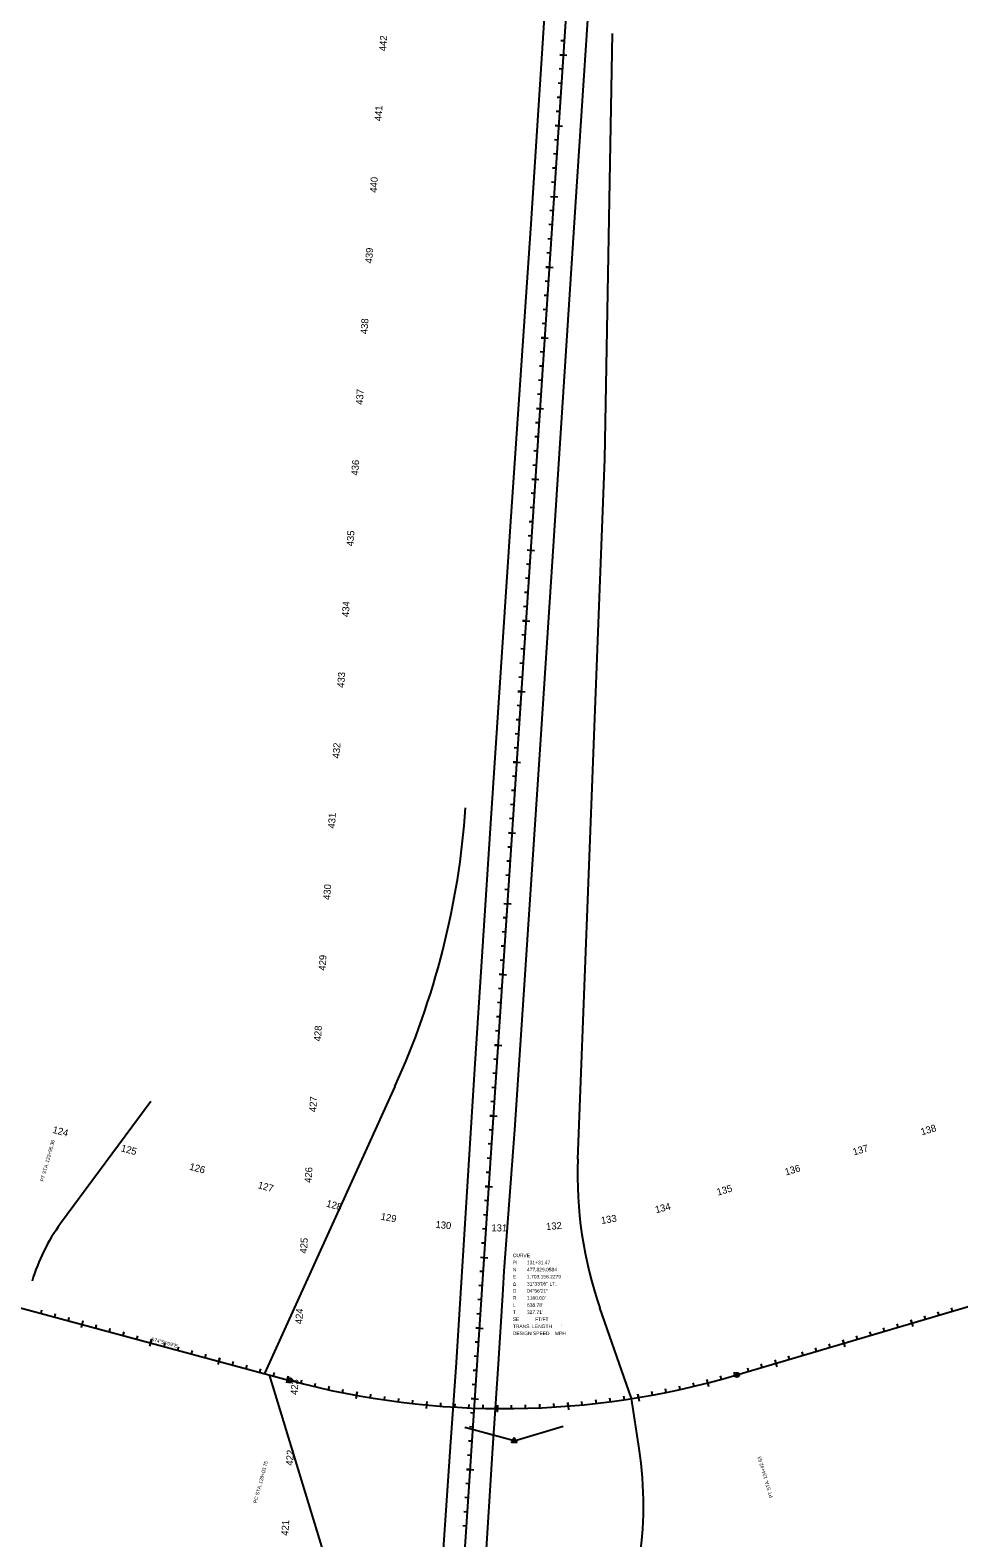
# Model space of a CAD drawing. Extents: x 1699999 to 1705087, y 475568 to 482652.
# Drawn here: x 1702475 to 1703786, y 477692 to 479819 of the extents above; entities that cross this region are included whole.
import ezdxf

# ---------------------------------------------------------------- set-up
doc = ezdxf.new("R2010")
doc.units = 0
for name, color, linetype in [('Default', 7, 'Continuous'), ('DES - DTM - Boundary', 7, 'Continuous'), ('DES - DTM - Ground', 7, 'Continuous'), ('DES - DTM - Points - High', 7, 'Continuous'), ('DESIGN - TYPICAL - Guardrail', 7, 'Continuous'), ('TC_Aggregate', 7, 'Continuous')]:
    doc.layers.add(name, color=color, linetype=linetype)

msp = doc.modelspace()

# ---------------------------------------------------------------- linework, layer by layer
at = {"layer": 'Default'}
for p, q in [((1703065.1, 477316.2), (1703415.3, 482625.1)), ((1703248.2, 478226.2), (1703286, 479214.2)), ((1702990, 478329), (1702806, 477924)), ((1703129.1, 478287.3), (1703129.1, 478286.5)), ((1702447.5, 478020.6), (1702841.8, 477914.3)), ((1703323.8, 477888.5), (1703279.3, 478016.7)), ((1703334.6, 477818.2), (1703323.8, 477888.5))]:
    msp.add_line(p, q, dxfattribs=at)
for centre, radius, start, end in [((1703820.7, 478204.3), 573, 177.8081, 199.1047), ((1702727.8, 477980.8), 260.4, 143.5571, 163.5778), ((1703143.6, 479034.4), 1160, 254.9193, 286.4705), ((1702819.9, 477738.6), 520.9, 332.348, 8.7908)]:
    msp.add_arc(centre, radius, start, end, dxfattribs=at)
at = {"layer": 'DES - DTM - Ground'}
for p, q in [((1703065.1, 477316.2), (1703415.3, 482625.1)), ((1703286, 479214.2), (1703297, 479814.6)), ((1703248.2, 478226.2), (1703286, 479214.2)), ((1702990, 478329), (1702806, 477924)), ((1703472.5, 477922), (1704846.9, 478328.4)), ((1702645.4, 478307.7), (1702518.3, 478135.5)), ((1702447.5, 478020.6), (1702841.8, 477914.3)), ((1703323.8, 477888.5), (1703279.3, 478016.7)), ((1702812.7, 477922.2), (1702891.6, 477662.9)), ((1703334.6, 477818.2), (1703323.8, 477888.5))]:
    msp.add_line(p, q, dxfattribs=at)
for points in [[(1703117.2, 477646.5), (1703128.4, 477818.7), (1703136.1, 477937.6), (1703142.4, 478034.3), (1703144.2, 478068.5), (1703147.9, 478118.3), (1703159.1, 478267.9), (1703195.1, 478804.3), (1703212.4, 479069.6), (1703246.7, 479598.7), (1703259.7, 479798.3), (1703310.9, 480575.7)], [(1702792.5, 475614.8), (1702811.9, 475706.1), (1702823.5, 475760.9), (1702852.3, 475908.3), (1702864.3, 475969.8), (1702898.6, 476166.8), (1702930.7, 476366.1), (1702944.7, 476465.1), (1702959.1, 476566.7), (1702978.3, 476715.2), (1702996.2, 476873.4), (1703005.9, 476974.9), (1703015.7, 477085.1), (1703027.3, 477226.9), (1703041.4, 477426.6), (1703058.8, 477682.8), (1703068.5, 477820.5), (1703076.7, 477939.3), (1703102.2, 478346.2), (1703125.6, 478707.3), (1703153.6, 479126.1), (1703182.2, 479545.9), (1703224.8, 480202.3)]]:
    msp.add_lwpolyline(points, dxfattribs=at)
for centre, radius, start, end in [((1701946.8, 478803.1), 1145.9, 335.5607, 355.9395), ((1703820.7, 478204.3), 573, 177.8081, 199.1047), ((1702727.8, 477980.8), 260.4, 143.5571, 163.5778), ((1703143.6, 479034.4), 1160, 254.9193, 286.4705), ((1702819.9, 477738.6), 520.9, 332.348, 8.7908)]:
    msp.add_arc(centre, radius, start, end, dxfattribs=at)
at = {"layer": 'DES - DTM - Points - High'}
for p, q in [((1703229.2, 479804), (1703224.2, 479804.4)), ((1703222.9, 479784.4), (1703232.8, 479783.8)), ((1703226.5, 479764.1), (1703221.6, 479764.5)), ((1703223.9, 479724.2), (1703218.9, 479724.5)), ((1703225.2, 479744.2), (1703220.2, 479744.5)), ((1703222.6, 479704.3), (1703217.6, 479704.6)), ((1703216.3, 479684.6), (1703226.3, 479684)), ((1703219.9, 479664.3), (1703215, 479664.7)), ((1703218.6, 479644.4), (1703213.7, 479644.7)), ((1703217.3, 479624.4), (1703212.3, 479624.8)), ((1703216, 479604.5), (1703211, 479604.8)), ((1703209.7, 479584.8), (1703219.7, 479584.2)), ((1703213.4, 479564.6), (1703208.4, 479564.9)), ((1703212, 479544.6), (1703207.1, 479544.9)), ((1703210.7, 479524.6), (1703205.8, 479525)), ((1703209.4, 479504.7), (1703204.4, 479505)), ((1703203.1, 479485.1), (1703213.1, 479484.4)), ((1703206.8, 479464.8), (1703201.8, 479465.1)), ((1703205.5, 479444.8), (1703200.5, 479445.1)), ((1703202.8, 479404.9), (1703197.9, 479405.2)), ((1703204.1, 479424.9), (1703199.2, 479425.2)), ((1703196.5, 479385.3), (1703206.5, 479384.6)), ((1703200.2, 479365), (1703195.2, 479365.3)), ((1703198.9, 479345), (1703193.9, 479345.4)), ((1703197.6, 479325.1), (1703192.6, 479325.4)), ((1703196.3, 479305.1), (1703191.3, 479305.5)), ((1703189.9, 479285.5), (1703199.9, 479284.8)), ((1703193.6, 479265.2), (1703188.6, 479265.5)), ((1703192.3, 479245.3), (1703187.3, 479245.6)), ((1703191, 479225.3), (1703186, 479225.6)), ((1703189.7, 479205.3), (1703184.7, 479205.7)), ((1703183.4, 479185.7), (1703193.3, 479185.1)), ((1703187, 479165.4), (1703182.1, 479165.8)), ((1703185.7, 479145.5), (1703180.8, 479145.8)), ((1703184.4, 479125.5), (1703179.4, 479125.8)), ((1703183.1, 479105.6), (1703178.1, 479105.9)), ((1703180.5, 479065.6), (1703175.5, 479066)), ((1703176.8, 479085.9), (1703186.8, 479085.3)), ((1703179.1, 479045.7), (1703174.2, 479046)), ((1703177.8, 479025.7), (1703172.9, 479026.1)), ((1703176.5, 479005.8), (1703171.5, 479006.1)), ((1703170.2, 478986.1), (1703180.2, 478985.5)), ((1703173.9, 478965.9), (1703168.9, 478966.2)), ((1703172.6, 478945.9), (1703167.6, 478946.2)), ((1703171.2, 478925.9), (1703166.3, 478926.3)), ((1703169.9, 478906), (1703165, 478906.3)), ((1703163.6, 478886.4), (1703173.6, 478885.7)), ((1703167.3, 478866.1), (1703162.3, 478866.4)), ((1703166, 478846.1), (1703161, 478846.4)), ((1703164.7, 478826.2), (1703159.7, 478826.5)), ((1703163.3, 478806.2), (1703158.4, 478806.5)), ((1703157, 478786.6), (1703167, 478785.9)), ((1703159.4, 478746.3), (1703154.4, 478746.7)), ((1703160.7, 478766.3), (1703155.7, 478766.6)), ((1703158.1, 478726.4), (1703153.1, 478726.7)), ((1703156.8, 478706.4), (1703151.8, 478706.8)), ((1703150.5, 478686.8), (1703160.4, 478686.1)), ((1703154.1, 478666.5), (1703149.2, 478666.8)), ((1703152.8, 478646.6), (1703147.8, 478646.9)), ((1703151.5, 478626.6), (1703146.5, 478626.9)), ((1703150.2, 478606.6), (1703145.2, 478607)), ((1703143.9, 478587), (1703153.8, 478586.4)), ((1703147.5, 478566.7), (1703142.6, 478567.1)), ((1703146.2, 478546.8), (1703141.3, 478547.1)), ((1703144.9, 478526.8), (1703139.9, 478527.1)), ((1703143.6, 478506.9), (1703138.6, 478507.2)), ((1703137.3, 478487.2), (1703147.3, 478486.6)), ((1703141, 478466.9), (1703136, 478467.3)), ((1703138.3, 478427), (1703133.4, 478427.4)), ((1703139.6, 478447), (1703134.7, 478447.3)), ((1703137, 478407.1), (1703132, 478407.4)), ((1703130.7, 478387.4), (1703140.7, 478386.8)), ((1703134.4, 478367.2), (1703129.4, 478367.5)), ((1703133.1, 478347.2), (1703128.1, 478347.5)), ((1703131.7, 478327.2), (1703126.8, 478327.6)), ((1703130.4, 478307.3), (1703125.5, 478307.6)), ((1703124.1, 478287.7), (1703134.1, 478287)), ((1703127.8, 478267.4), (1703122.8, 478267.7)), ((1703126.5, 478247.4), (1703121.5, 478247.8)), ((1703125.2, 478227.5), (1703120.2, 478227.8)), ((1703123.8, 478207.5), (1703118.9, 478207.8)), ((1703117.5, 478187.9), (1703127.5, 478187.2)), ((1703121.2, 478167.6), (1703116.2, 478167.9)), ((1703119.9, 478147.6), (1703114.9, 478148)), ((1703117.3, 478107.7), (1703112.3, 478108.1)), ((1703118.6, 478127.7), (1703113.6, 478128)), ((1703111, 478088.1), (1703120.9, 478087.4)), ((1703114.6, 478067.8), (1703109.7, 478068.1)), ((1703113.3, 478047.9), (1703108.3, 478048.2)), ((1703112, 478027.9), (1703107, 478028.2)), ((1702490.6, 478009), (1702491.9, 478013.8)), ((1702509.9, 478003.8), (1702511.2, 478008.6)), ((1702529.2, 477998.6), (1702530.5, 478003.4)), ((1703110.7, 478007.9), (1703105.7, 478008.3)), ((1703738.6, 478000.7), (1703737.2, 478005.4)), ((1703757.8, 478006.3), (1703756.3, 478011.1)), ((1703776.9, 478012), (1703775.5, 478016.8)), ((1702549.8, 477998.2), (1702547.2, 477988.5)), ((1702567.8, 477988.1), (1702569.1, 477993)), ((1702587.1, 477982.9), (1702588.4, 477987.8)), ((1702606.4, 477977.7), (1702607.7, 477982.6)), ((1703104.4, 477988.3), (1703114.4, 477987.7)), ((1703661.9, 477978), (1703660.4, 477982.7)), ((1703681, 477983.6), (1703679.6, 477988.4)), ((1703700.2, 477989.3), (1703698.8, 477994.1)), ((1703718, 477999.8), (1703720.8, 477990.2)), ((1702625.8, 477972.5), (1702627, 477977.3)), ((1702646.4, 477972.2), (1702643.8, 477962.5)), ((1702664.4, 477962.1), (1702665.7, 477966.9)), ((1702683.7, 477956.9), (1702685, 477961.7)), ((1703108, 477968), (1703103.1, 477968.4)), ((1703585.1, 477955.3), (1703583.7, 477960.1)), ((1703604.3, 477961), (1703602.9, 477965.7)), ((1703622.1, 477971.4), (1703624.9, 477961.8)), ((1703642.7, 477972.3), (1703641.3, 477977.1)), ((1702703, 477951.7), (1702704.3, 477956.5)), ((1702722.3, 477946.5), (1702723.6, 477951.3)), ((1702742.9, 477946.1), (1702740.3, 477936.5)), ((1702760.9, 477936.1), (1702762.2, 477940.9)), ((1703106.7, 477948.1), (1703101.8, 477948.4)), ((1703526.2, 477943.1), (1703529, 477933.5)), ((1703546.8, 477943.9), (1703545.4, 477948.7)), ((1703566, 477949.6), (1703564.5, 477954.4)), ((1702780.2, 477930.9), (1702781.5, 477935.7)), ((1702799.6, 477925.7), (1702800.9, 477930.5)), ((1702818.9, 477920.5), (1702820.2, 477925.3)), ((1702839.5, 477920.1), (1702836.9, 477910.5)), ((1703105.4, 477928.1), (1703100.4, 477928.4)), ((1703450.8, 477915.8), (1703449.5, 477920.6)), ((1703470.1, 477921.3), (1703468.7, 477926)), ((1703489.2, 477926.9), (1703487.8, 477931.7)), ((1703508.4, 477932.6), (1703507, 477937.4)), ((1702857.5, 477910.2), (1702858.7, 477915)), ((1702876.9, 477905.4), (1702878.1, 477910.3)), ((1702896.4, 477901), (1702897.5, 477905.9)), ((1702916, 477896.9), (1702917, 477901.8)), ((1702936.6, 477898.1), (1702934.8, 477888.2)), ((1703104.1, 477908.2), (1703099.1, 477908.5)), ((1703332.9, 477895), (1703334.5, 477885.1)), ((1703353.4, 477893.5), (1703352.5, 477898.4)), ((1703373, 477897.3), (1703372, 477902.2)), ((1703392.6, 477901.4), (1703391.5, 477906.3)), ((1703412.1, 477905.9), (1703410.9, 477910.7)), ((1703430.3, 477915.5), (1703432.7, 477905.8)), ((1702955.4, 477889.7), (1702956.2, 477894.7)), ((1702975.1, 477886.7), (1702975.9, 477891.6)), ((1702994.9, 477883.9), (1702995.6, 477888.9)), ((1703014.8, 477881.5), (1703015.4, 477886.5)), ((1703035.2, 477884.5), (1703034.2, 477874.5)), ((1703054.6, 477877.8), (1703055, 477882.8)), ((1703074.6, 477876.4), (1703074.9, 477881.4)), ((1703094.5, 477875.4), (1703094.8, 477880.4)), ((1703097.8, 477888.5), (1703107.8, 477887.9)), ((1703114.5, 477874.7), (1703114.7, 477879.7)), ((1703134.6, 477879.4), (1703134.5, 477869.4)), ((1703154.5, 477874.4), (1703154.5, 477879.4)), ((1703174.5, 477874.8), (1703174.4, 477879.8)), ((1703194.5, 477875.5), (1703194.3, 477880.5)), ((1703214.5, 477876.5), (1703214.2, 477881.5)), ((1703234.1, 477882.9), (1703234.8, 477872.9)), ((1703254.4, 477879.7), (1703253.9, 477884.6)), ((1703274.3, 477881.8), (1703273.7, 477886.7)), ((1703294.1, 477884.2), (1703293.5, 477889.1)), ((1703313.9, 477886.9), (1703313.2, 477891.9)), ((1703101.5, 477868.2), (1703096.5, 477868.6)), ((1703100.2, 477848.3), (1703095.2, 477848.6)), ((1703098.8, 477828.3), (1703093.9, 477828.7)), ((1703091.2, 477788.7), (1703101.2, 477788.1)), ((1703097.5, 477808.4), (1703092.5, 477808.7)), ((1703094.9, 477768.5), (1703089.9, 477768.8)), ((1703093.6, 477748.5), (1703088.6, 477748.8)), ((1703092.3, 477728.5), (1703087.3, 477728.9)), ((1703090.9, 477708.6), (1703086, 477708.9))]:
    msp.add_line(p, q, dxfattribs=at)
at = {"layer": 'DESIGN - TYPICAL - Guardrail'}
for p, q in [((1703227.8, 479784.1), (1703222.9, 479784.4)), ((1703221.3, 479684.3), (1703216.3, 479684.6)), ((1703209.7, 479584.8), (1703219.7, 479584.2)), ((1703208.1, 479484.7), (1703203.1, 479485.1)), ((1703201.5, 479385), (1703196.5, 479385.3)), ((1703194.9, 479285.2), (1703190, 479285.5)), ((1703188.4, 479185.4), (1703183.4, 479185.7)), ((1703176.8, 479085.9), (1703186.8, 479085.3)), ((1703175.2, 478985.8), (1703170.2, 478986.1)), ((1703168.6, 478886), (1703163.6, 478886.4)), ((1703162, 478786.3), (1703157.1, 478786.6)), ((1703155.4, 478686.5), (1703150.5, 478686.8)), ((1703143.9, 478587), (1703153.9, 478586.4)), ((1703142.3, 478486.9), (1703137.3, 478487.2)), ((1703135.7, 478387.1), (1703130.7, 478387.4)), ((1703129.1, 478287.3), (1703124.1, 478287.7)), ((1703122.5, 478187.6), (1703117.6, 478187.9)), ((1703111, 478088.1), (1703121, 478087.4)), ((1702549.8, 477998.2), (1702547.2, 477988.5)), ((1703109.4, 477988), (1703104.4, 477988.3)), ((1703719.4, 477995), (1703718, 477999.8)), ((1702645.1, 477967.3), (1702646.4, 477972.1)), ((1703623.5, 477966.6), (1703622.1, 477971.4)), ((1702741.6, 477941.3), (1702742.9, 477946.1)), ((1703526.2, 477943.1), (1703529, 477933.5)), ((1702838.2, 477915.3), (1702839.5, 477920.1)), ((1702935.7, 477893.2), (1702936.6, 477898.1)), ((1703333.7, 477890), (1703332.9, 477895)), ((1703431.5, 477910.7), (1703430.3, 477915.5)), ((1703035.2, 477884.5), (1703034.2, 477874.5)), ((1703102.8, 477888.2), (1703097.8, 477888.5)), ((1703134.5, 477874.4), (1703134.6, 477879.4)), ((1703234.4, 477877.9), (1703234.1, 477882.9)), ((1703096.2, 477788.4), (1703091.2, 477788.7))]:
    msp.add_line(p, q, dxfattribs=at)
for centre, radius in [((1702841.8, 477914.3), 3.14), ((1703472.5, 477922), 3.14), ((1703472.5, 477922), 0.33), ((1702841.8, 477914.3), 0.33)]:
    msp.add_circle(centre, radius, dxfattribs=at)
at = {"layer": 'TC_Aggregate'}
for q in [(1703088.7, 477847.8), (1703227.3, 477849.5), (1703158.2, 477829.1)]:
    msp.add_line((1703158.2, 477829.1), q, dxfattribs=at)
msp.add_lwpolyline([(1703158.2, 477833.2), (1703154.7, 477826.9), (1703161.9, 477827)], close=True, dxfattribs=at)

# ---------------------------------------------------------------- texts
at = {"layer": 'DES - DTM - Boundary'}
for s, rotation, p in [('123+95.36', 74.9193, (1702501.5, 478221.1)), (' STA. ', 74.9193, (1702496.6, 478203)), ('PT', 74.9193, (1702494.3, 478194.4)), ('128+03.75', 74.9193, (1702802.4, 477768)), ('134+42.53', 106.4705, (1703515.7, 477775.9)), (' STA. ', 106.4705, (1703521, 477757.9)), ('PC', 74.9193, (1702795, 477740.5)), (' STA. ', 74.9193, (1702797.5, 477749.9)), ('PT', 106.4705, (1703523.5, 477749.4))]:
    msp.add_text(s, height=4.98, rotation=rotation, dxfattribs=at).set_placement(p)
for s, p in [('CURVE    ', (1703156.4, 478088.1)), ('PI', (1703156.4, 478078.1)), ('N', (1703156.4, 478068.1)), ('477,829.0584', (1703176.4, 478068.1)), ('131+31.47', (1703176.4, 478078.1)), ('Δ', (1703156.4, 478048.1)), ('E', (1703156.4, 478058.1)), ('31°33\'05"', (1703176.4, 478048.1)), ('1,703,158.2279', (1703176.4, 478058.1)), (' LT.', (1703206.3, 478048.1)), ('D', (1703156.4, 478038.1)), ('R', (1703156.4, 478028.1)), ('L', (1703156.4, 478018.1)), ('04°56\'21"', (1703176.4, 478038.1)), ("638.78'", (1703176.4, 478018.1)), ("1160.00'", (1703176.4, 478028.1)), ('T', (1703156.4, 478008.1)), ('SE', (1703156.4, 477998.1)), ("327.71'", (1703176.4, 478008.1)), ('      FT/FT', (1703176.4, 477998.1)), ("TRANS. LENGTH       '", (1703156.4, 477988.1)), ('DESIGN SPEED    MPH', (1703156.4, 477978.1))]:
    msp.add_text(s, height=5, dxfattribs=at).set_placement(p)
at = {"layer": 'DES - DTM - Points - High'}
for s, rotation, p in [('442', 86.2259, (1702977.6, 479789.3)), ('441', 86.2259, (1702971.1, 479690.5)), ('440', 86.2259, (1702964.5, 479589.7)), ('439', 86.2259, (1702957.9, 479489.9)), ('438', 86.2259, (1702951.3, 479390.1)), ('437', 86.2259, (1702944.7, 479290.4)), ('436', 86.2259, (1702938.2, 479190.6)), ('435', 86.2259, (1702931.6, 479090.8)), ('434', 86.2259, (1702925, 478991)), ('433', 86.2259, (1702918.4, 478891.2)), ('432', 86.2259, (1702911.8, 478791.5)), ('431', 86.2259, (1702905.3, 478692.6)), ('430', 86.2259, (1702898.7, 478591.9)), ('429', 86.2259, (1702892.1, 478492.1)), ('428', 86.2259, (1702885.5, 478392.3)), ('427', 86.2259, (1702878.9, 478292.5)), ('124', 344.9193, (1702506.1, 478263.7)), ('138', 16.4735, (1703733.6, 478259.9)), ('125', 344.9193, (1702602.6, 478237.7)), ('137', 16.4735, (1703637.7, 478231.5)), ('126', 344.9193, (1702699.2, 478211.7)), ('426', 86.2259, (1702872.3, 478192.7)), ('136', 16.4735, (1703541.8, 478203.2)), ('127', 344.9193, (1702795.8, 478185.6)), ('135', 16.4735, (1703445.8, 478174.8)), ('128', 344.9193, (1702892.3, 478159.6)), ('129', 349.6732, (1702969.4, 478141.1)), ('134', 14.3697, (1703358.5, 478150)), ('130', 354.6125, (1703046.9, 478129.5)), ('131', 359.5518, (1703126.2, 478124.5)), ('132', 4.4911, (1703203.7, 478126.3)), ('133', 9.4304, (1703281.6, 478134.8)), ('425', 86.2259, (1702865.7, 478092.9)), ('424', 86.2259, (1702859.2, 477993.2)), ('423', 86.2259, (1702852.6, 477893.4)), ('422', 86.2259, (1702846, 477793.7)), ('421', 86.2259, (1702839.5, 477694.8))]:
    msp.add_text(s, height=9.96, rotation=rotation, dxfattribs=at).set_placement(p)
at = {"layer": 'DESIGN - TYPICAL - Guardrail'}
for s, rotation, p in [('440', 86.2259, (1702964.5, 479589.7)), ('435', 86.2259, (1702931.6, 479090.8)), ('430', 86.2259, (1702898.7, 478591.9)), ('125', 344.9193, (1702602.6, 478237.7)), ('135', 16.4735, (1703445.8, 478174.8)), ('130', 354.6125, (1703046.9, 478129.5)), ('425', 86.2259, (1702865.7, 478092.9))]:
    msp.add_text(s, height=9.96, rotation=rotation, dxfattribs=at).set_placement(p)
at = {"layer": 'TC_Aggregate'}
msp.add_text('S74°55\'09"E', height=4.98, rotation=344.9193, dxfattribs=at).set_placement((1702645.4, 477970.3))

doc.saveas('drawing.dxf')
